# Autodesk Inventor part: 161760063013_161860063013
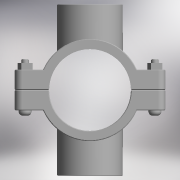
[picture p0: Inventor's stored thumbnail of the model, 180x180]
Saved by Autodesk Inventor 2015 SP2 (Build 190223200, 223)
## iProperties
Created: 2017-05
Part Number: 161760063013_161860063013
Material: Generic
Description: PLASSON DOUBLE SADDLE 63-1.1/4"
Document SubType Name: Modeling
Designer: KIM
Density: 1 g/cm^3
Appearance: Default
Author: KIM
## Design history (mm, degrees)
derived "16176.ipt"
feature "Solid1::16176.ipt"
feature "Solid2::16176.ipt"
tag "TaggingFeature1"
body "Solid1"
body "Solid2"
other parameters: "d0" = 78.75, "d1" = 116, "d2" = 31.5, "d3" = 63, "d4" = 84, "d5" = 0, "d6" = 5.8, "d7" = 116, "d8" = 0.1, "d10" = 0, "d11" = 0.63, "d20" = 0.63, "d23" = 0.63, "d37" = 8, "d38" = 39.5, "d39" = 0, "d40" = 3, "d41" = 5, "d42" = 0, "d43" = 6, "d44" = 3, "d45" = 0, "d46" = 0.63, "d52" = 38.952, "d53" = 25, "d54" = 0, "d55" = 32, "d57" = 0, "d58" = 68.04, "d60" = 0, "d63" = 8, "d66" = 68, "d67" = 132, "d68" = 50.6376, "d69" = 38.952, "d70" = 25, "d71" = 0, "d72" = 32, "d74" = 0, "d75" = 0.63, "d_" = 63, "B_" = 32, "G_" = 38.952, "A_" = 66, "L_" = 116, "L_1" = 84, "l_2" = 25
